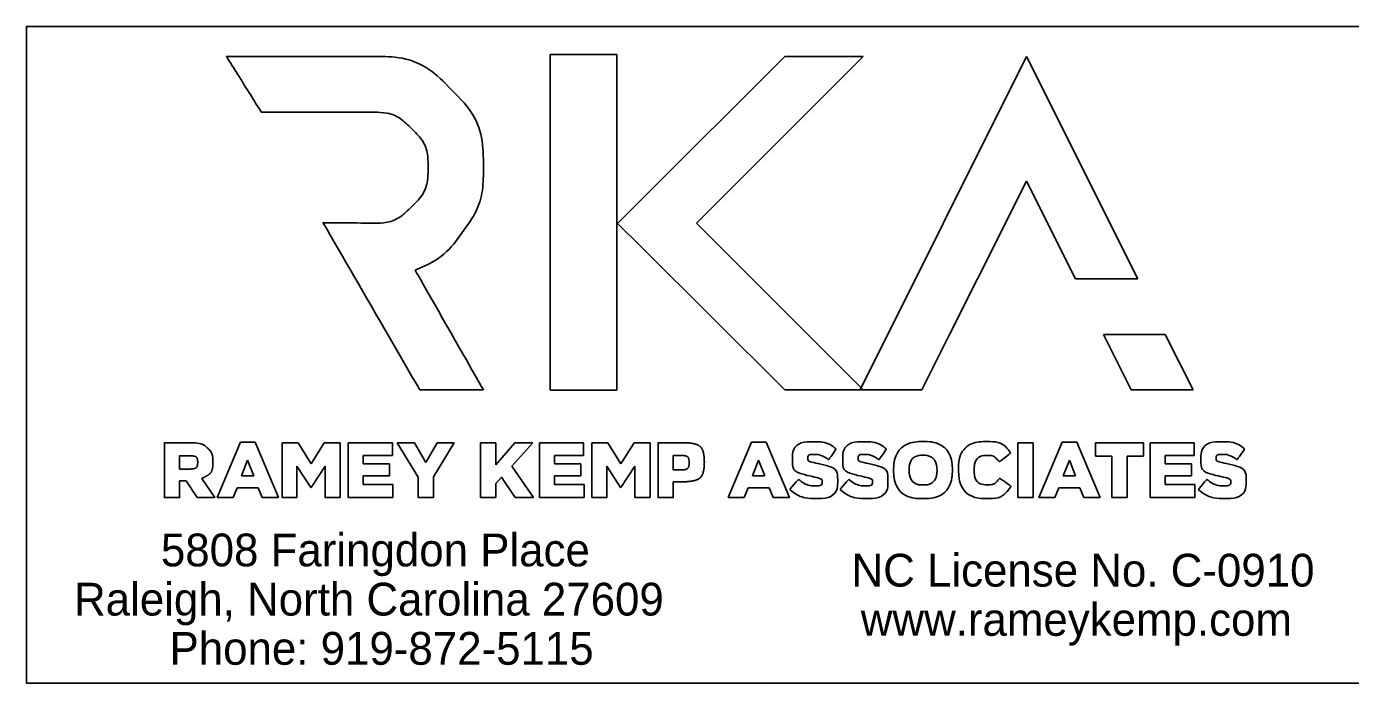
# Model space of a CAD drawing. Extents: x 573078 to 573156.2, y -55225.7 to -55195.8.
# Drawn here: x 573104.512 to 573107.444, y -55197.257 to -55195.798 of the extents above; entities that cross this region are included whole.
import ezdxf

# ---------------------------------------------------------------- set-up
doc = ezdxf.new("R2010")
doc.units = 0
for name, color, linetype in [('Old_Level_60', 7, 'Continuous'), ('Old_Level_61', 7, 'Continuous'), ('Old_Level_62', 7, 'Continuous'), ('Old_Level_63', 7, 'Continuous'), ('Sheet North Arrow Point CELL', 7, 'Continuous'), ('Sheet Plan CELL', 7, 'Continuous')]:
    doc.layers.add(name, color=color, linetype=linetype)

msp = doc.modelspace()

# ---------------------------------------------------------------- linework, layer by layer
at = {"layer": 'Old_Level_60'}
for p, q in [((573105.8198, -55195.8604), (573105.6721, -55195.8604)), ((573105.6721, -55195.8604), (573105.6721, -55196.6033)), ((573105.8198, -55196.6033), (573105.8198, -55195.8604)), ((573105.8727, -55196.183), (573106.1918, -55195.8648)), ((573106.3651, -55195.8648), (573105.9962, -55196.2337)), ((573106.1918, -55195.8648), (573106.3651, -55195.8648)), ((573106.3583, -55196.6026), (573106.7272, -55195.8648)), ((573106.7272, -55195.8648), (573106.9734, -55196.3573)), ((573106.7272, -55196.1406), (573106.6184, -55196.3573)), ((573106.8351, -55196.3573), (573106.7272, -55196.1406)), ((573105.821, -55196.2346), (573105.8727, -55196.183)), ((573105.8727, -55196.2854), (573105.821, -55196.2346)), ((573105.9962, -55196.2337), (573106.3651, -55196.6026)), ((573106.1918, -55196.6026), (573105.8727, -55196.2854)), ((573106.6184, -55196.3573), (573106.5575, -55196.479)), ((573106.9734, -55196.3573), (573106.8351, -55196.3573)), ((573106.5575, -55196.479), (573106.4948, -55196.6026)), ((573105.6721, -55196.6033), (573105.8198, -55196.6033)), ((573106.3651, -55196.6026), (573106.1918, -55196.6026)), ((573106.4948, -55196.6026), (573106.3583, -55196.6026))]:
    msp.add_line(p, q, dxfattribs=at)
msp.add_open_spline([(573105.3731, -55196.3379), (573105.3731, -55196.3379), (573105.5243, -55196.6026), (573105.5243, -55196.6026), (573105.5243, -55196.6026), (573105.3832, -55196.6026), (573105.3832, -55196.6026), (573105.3832, -55196.6026), (573105.1692, -55196.2328), (573105.1692, -55196.2328), (573105.1692, -55196.2328), (573105.279, -55196.2337), (573105.279, -55196.2337), (573105.3122, -55196.2337), (573105.3408, -55196.2217), (573105.3648, -55196.1978), (573105.3897, -55196.1738), (573105.4017, -55196.1443), (573105.4017, -55196.1101), (573105.4017, -55196.0769), (573105.3897, -55196.0484), (573105.3648, -55196.0244), (573105.3408, -55196.0004), (573105.3122, -55195.9884), (573105.279, -55195.9884), (573105.279, -55195.9884), (573105.0328, -55195.9884), (573105.0328, -55195.9884), (573105.0328, -55195.9884), (573104.9553, -55195.8648), (573104.9553, -55195.8648), (573104.9553, -55195.8648), (573105.279, -55195.8648), (573105.279, -55195.8648), (573105.3463, -55195.8648), (573105.4044, -55195.8888), (573105.4524, -55195.9368), (573105.5003, -55195.9856), (573105.5243, -55196.0428), (573105.5243, -55196.1101), (573105.5243, -55196.1618), (573105.5105, -55196.2079), (573105.481, -55196.2494), (573105.4524, -55196.2909), (573105.4164, -55196.3204), (573105.3731, -55196.3379)], degree=3, dxfattribs=at)
at = {"layer": 'Old_Level_61'}
for p, q in [((573106.9587, -55196.6026), (573106.8978, -55196.48)), ((573106.8978, -55196.48), (573107.0343, -55196.48)), ((573107.0343, -55196.48), (573107.0961, -55196.6026)), ((573107.0961, -55196.6026), (573106.9587, -55196.6026))]:
    msp.add_line(p, q, dxfattribs=at)
at = {"layer": 'Old_Level_62'}
for p, q in [((573104.9345, -55196.8412), (573104.9862, -55196.7189)), ((573104.9862, -55196.7189), (573105.0186, -55196.7189)), ((573105.0186, -55196.7189), (573105.0703, -55196.8412)), ((573105.0783, -55196.7198), (573105.1138, -55196.7198)), ((573105.0783, -55196.8412), (573105.0783, -55196.7198)), ((573105.1138, -55196.7198), (573105.1428, -55196.7668)), ((573105.1428, -55196.7668), (573105.1718, -55196.7198)), ((573105.1718, -55196.7198), (573105.2073, -55196.7198)), ((573105.2073, -55196.7198), (573105.2073, -55196.8412)), ((573105.225, -55196.7198), (573105.3226, -55196.7198)), ((573105.225, -55196.8412), (573105.225, -55196.7198)), ((573105.3226, -55196.7198), (573105.3226, -55196.7484)), ((573105.3796, -55196.7958), (573105.3335, -55196.7198)), ((573105.3335, -55196.7198), (573105.3718, -55196.7198)), ((573105.3718, -55196.7198), (573105.3968, -55196.764)), ((573105.3968, -55196.764), (573105.4219, -55196.7198)), ((573105.4596, -55196.7198), (573105.4134, -55196.7953)), ((573105.4219, -55196.7198), (573105.4596, -55196.7198)), ((573105.518, -55196.7198), (573105.5517, -55196.7198)), ((573105.518, -55196.8412), (573105.518, -55196.7198)), ((573105.5517, -55196.7198), (573105.5517, -55196.7691)), ((573105.5517, -55196.7691), (573105.5935, -55196.7198)), ((573105.6334, -55196.7198), (573105.5874, -55196.772)), ((573105.5935, -55196.7198), (573105.6334, -55196.7198)), ((573105.6486, -55196.7198), (573105.7462, -55196.7198)), ((573105.6486, -55196.8412), (573105.6486, -55196.7198)), ((573105.7462, -55196.7198), (573105.7462, -55196.7484)), ((573105.7643, -55196.7198), (573105.7999, -55196.7198)), ((573105.7643, -55196.8412), (573105.7643, -55196.7198)), ((573105.7999, -55196.7198), (573105.8288, -55196.7668)), ((573105.8288, -55196.7668), (573105.8578, -55196.7198)), ((573105.8578, -55196.7198), (573105.8934, -55196.7198)), ((573105.8934, -55196.7198), (573105.8934, -55196.8412)), ((573106.0661, -55196.8412), (573106.1178, -55196.7189)), ((573106.1178, -55196.7189), (573106.1502, -55196.7189)), ((573106.1502, -55196.7189), (573106.2019, -55196.8412)), ((573106.708, -55196.7198), (573106.7418, -55196.7198)), ((573106.708, -55196.8412), (573106.708, -55196.7198)), ((573106.7418, -55196.7198), (573106.7418, -55196.8412)), ((573106.7543, -55196.8412), (573106.806, -55196.7189)), ((573106.806, -55196.7189), (573106.8385, -55196.7189)), ((573106.8385, -55196.7189), (573106.8902, -55196.8412)), ((573106.8796, -55196.7493), (573106.8796, -55196.7198)), ((573106.8796, -55196.7198), (573106.9861, -55196.7198)), ((573106.9861, -55196.7198), (573106.9861, -55196.7493)), ((573107.0008, -55196.7198), (573107.0985, -55196.7198)), ((573107.0008, -55196.8412), (573107.0008, -55196.7198)), ((573107.0985, -55196.7198), (573107.0985, -55196.7484)), ((573104.8916, -55196.7637), (573104.8916, -55196.7633)), ((573104.9254, -55196.7613), (573104.9254, -55196.7616)), ((573105.0022, -55196.7588), (573104.9885, -55196.7934)), ((573105.0157, -55196.7934), (573105.0022, -55196.7588)), ((573105.3226, -55196.7484), (573105.2583, -55196.7484)), ((573105.2583, -55196.7484), (573105.2583, -55196.7668)), ((573105.7462, -55196.7484), (573105.6819, -55196.7484)), ((573105.6819, -55196.7484), (573105.6819, -55196.7668)), ((573105.9799, -55196.7644), (573105.9799, -55196.764)), ((573106.0135, -55196.7625), (573106.0135, -55196.7628)), ((573106.1338, -55196.7588), (573106.12, -55196.7934)), ((573106.1473, -55196.7934), (573106.1338, -55196.7588)), ((573106.822, -55196.7588), (573106.8083, -55196.7934)), ((573106.8355, -55196.7934), (573106.822, -55196.7588)), ((573106.916, -55196.7493), (573106.8796, -55196.7493)), ((573106.916, -55196.8412), (573106.916, -55196.7493)), ((573106.9861, -55196.7493), (573106.9497, -55196.7493)), ((573106.9497, -55196.7493), (573106.9497, -55196.8412)), ((573107.0985, -55196.7484), (573107.0342, -55196.7484)), ((573107.0342, -55196.7484), (573107.0342, -55196.7668)), ((573104.9885, -55196.7934), (573105.0157, -55196.7934)), ((573105.1421, -55196.819), (573105.1112, -55196.7718)), ((573105.1112, -55196.7718), (573105.1112, -55196.8412)), ((573105.1738, -55196.7715), (573105.1428, -55196.819)), ((573105.1738, -55196.8412), (573105.1738, -55196.7715)), ((573105.2583, -55196.7668), (573105.3166, -55196.7668)), ((573105.3166, -55196.7934), (573105.2583, -55196.7934)), ((573105.2583, -55196.7934), (573105.2583, -55196.8126)), ((573105.3166, -55196.7668), (573105.3166, -55196.7934)), ((573105.4134, -55196.7953), (573105.4134, -55196.8412)), ((573105.5874, -55196.772), (573105.635, -55196.8412)), ((573105.6819, -55196.7668), (573105.7402, -55196.7668)), ((573105.7402, -55196.7934), (573105.6819, -55196.7934)), ((573105.6819, -55196.7934), (573105.6819, -55196.8126)), ((573105.7402, -55196.7668), (573105.7402, -55196.7934)), ((573105.8281, -55196.819), (573105.7973, -55196.7718)), ((573105.7973, -55196.7718), (573105.7973, -55196.8412)), ((573105.8599, -55196.7715), (573105.8288, -55196.819)), ((573105.8599, -55196.8412), (573105.8599, -55196.7715)), ((573106.12, -55196.7934), (573106.1473, -55196.7934)), ((573106.4323, -55196.7809), (573106.4323, -55196.7805)), ((573106.4669, -55196.7802), (573106.4669, -55196.7805)), ((573106.5288, -55196.7809), (573106.5288, -55196.7805)), ((573106.5631, -55196.7802), (573106.5631, -55196.7805)), ((573106.8083, -55196.7934), (573106.8355, -55196.7934)), ((573107.0342, -55196.7668), (573107.0924, -55196.7668)), ((573107.0924, -55196.7934), (573107.0342, -55196.7934)), ((573107.0342, -55196.7934), (573107.0342, -55196.8126)), ((573107.0924, -55196.7668), (573107.0924, -55196.7934)), ((573104.9786, -55196.8195), (573104.9699, -55196.8412)), ((573105.0254, -55196.8195), (573104.9786, -55196.8195)), ((573105.0343, -55196.8412), (573105.0254, -55196.8195)), ((573105.1428, -55196.819), (573105.1421, -55196.819)), ((573105.2583, -55196.8126), (573105.3235, -55196.8126)), ((573105.3235, -55196.8126), (573105.3235, -55196.8412)), ((573105.3796, -55196.8412), (573105.3796, -55196.7958)), ((573105.564, -55196.7961), (573105.5517, -55196.8098)), ((573105.5517, -55196.8098), (573105.5517, -55196.8412)), ((573105.5946, -55196.8412), (573105.564, -55196.7961)), ((573105.6819, -55196.8126), (573105.7471, -55196.8126)), ((573105.7471, -55196.8126), (573105.7471, -55196.8412)), ((573105.8288, -55196.819), (573105.8281, -55196.819)), ((573106.1102, -55196.8195), (573106.1015, -55196.8412)), ((573106.157, -55196.8195), (573106.1102, -55196.8195)), ((573106.1658, -55196.8412), (573106.157, -55196.8195)), ((573106.7984, -55196.8195), (573106.7897, -55196.8412)), ((573106.8452, -55196.8195), (573106.7984, -55196.8195)), ((573106.8541, -55196.8412), (573106.8452, -55196.8195)), ((573107.0342, -55196.8126), (573107.0994, -55196.8126)), ((573107.0994, -55196.8126), (573107.0994, -55196.8412)), ((573104.9699, -55196.8412), (573104.9345, -55196.8412)), ((573105.0703, -55196.8412), (573105.0343, -55196.8412)), ((573105.1112, -55196.8412), (573105.0783, -55196.8412)), ((573105.2073, -55196.8412), (573105.1738, -55196.8412)), ((573105.3235, -55196.8412), (573105.225, -55196.8412)), ((573105.4134, -55196.8412), (573105.3796, -55196.8412)), ((573105.5517, -55196.8412), (573105.518, -55196.8412)), ((573105.635, -55196.8412), (573105.5946, -55196.8412)), ((573105.7471, -55196.8412), (573105.6486, -55196.8412)), ((573105.7973, -55196.8412), (573105.7643, -55196.8412)), ((573105.8934, -55196.8412), (573105.8599, -55196.8412)), ((573106.1015, -55196.8412), (573106.0661, -55196.8412)), ((573106.2019, -55196.8412), (573106.1658, -55196.8412)), ((573106.7418, -55196.8412), (573106.708, -55196.8412)), ((573106.7897, -55196.8412), (573106.7543, -55196.8412)), ((573106.8902, -55196.8412), (573106.8541, -55196.8412)), ((573106.9497, -55196.8412), (573106.916, -55196.8412)), ((573107.0994, -55196.8412), (573107.0008, -55196.8412))]:
    msp.add_line(p, q, dxfattribs=at)
for points in [[(573104.9004, -55196.7989), (573104.9294, -55196.8412), (573104.8905, -55196.8412), (573104.8661, -55196.8045), (573104.8657, -55196.8045), (573104.8513, -55196.8045), (573104.8513, -55196.8412), (573104.8177, -55196.8412), (573104.8177, -55196.7198), (573104.8751, -55196.7198)], [(573105.9613, -55196.8065), (573105.9447, -55196.8065), (573105.9447, -55196.8412), (573105.911, -55196.8412), (573105.911, -55196.7198), (573105.963, -55196.7198)], [(573104.8734, -55196.7489), (573104.8513, -55196.7489), (573104.8513, -55196.7781), (573104.8735, -55196.7781)], [(573105.9604, -55196.7481), (573105.9447, -55196.7481), (573105.9447, -55196.7802), (573105.9606, -55196.7802)]]:
    msp.add_lwpolyline(points, dxfattribs=at)
for points, degree in [([(573104.8751, -55196.7198), (573104.8937, -55196.7198), (573104.9065, -55196.7247), (573104.9147, -55196.733), (573104.9218, -55196.7399), (573104.9254, -55196.7493), (573104.9254, -55196.7613)], 3), ([(573105.963, -55196.7198), (573105.9937, -55196.7198), (573106.0135, -55196.7356), (573106.0135, -55196.7625)], 2), ([(573106.2028, -55196.8232), (573106.2028, -55196.8232), (573106.2215, -55196.8008), (573106.2215, -55196.8008), (573106.2335, -55196.8104), (573106.2469, -55196.8154), (573106.2609, -55196.8154), (573106.2699, -55196.8154), (573106.2748, -55196.8123), (573106.2748, -55196.8071), (573106.2748, -55196.8071), (573106.2748, -55196.8067), (573106.2748, -55196.8067), (573106.2748, -55196.8017), (573106.2708, -55196.7989), (573106.2543, -55196.7951), (573106.2285, -55196.7892), (573106.2085, -55196.7819), (573106.2085, -55196.7569), (573106.2085, -55196.7569), (573106.2085, -55196.7566), (573106.2085, -55196.7566), (573106.2085, -55196.734), (573106.2264, -55196.7177), (573106.2555, -55196.7177), (573106.2762, -55196.7177), (573106.2923, -55196.7233), (573106.3055, -55196.7339), (573106.3055, -55196.7339), (573106.2887, -55196.7576), (573106.2887, -55196.7576), (573106.2776, -55196.7498), (573106.2654, -55196.7456), (573106.2547, -55196.7456), (573106.2465, -55196.7456), (573106.2425, -55196.7491), (573106.2425, -55196.7535), (573106.2425, -55196.7535), (573106.2425, -55196.7538), (573106.2425, -55196.7538), (573106.2425, -55196.7594), (573106.2467, -55196.7618), (573106.2635, -55196.7656), (573106.2915, -55196.7717), (573106.3088, -55196.7807), (573106.3088, -55196.8034), (573106.3088, -55196.8034), (573106.3088, -55196.8038), (573106.3088, -55196.8038), (573106.3088, -55196.8286), (573106.2892, -55196.8433), (573106.2597, -55196.8433), (573106.2382, -55196.8433), (573106.2177, -55196.8366), (573106.2028, -55196.8232)], 3), ([(573106.3142, -55196.8232), (573106.3142, -55196.8232), (573106.3329, -55196.8008), (573106.3329, -55196.8008), (573106.3449, -55196.8104), (573106.3582, -55196.8154), (573106.3723, -55196.8154), (573106.3813, -55196.8154), (573106.3862, -55196.8123), (573106.3862, -55196.8071), (573106.3862, -55196.8071), (573106.3862, -55196.8067), (573106.3862, -55196.8067), (573106.3862, -55196.8017), (573106.3822, -55196.7989), (573106.3657, -55196.7951), (573106.3399, -55196.7892), (573106.3199, -55196.7819), (573106.3199, -55196.7569), (573106.3199, -55196.7569), (573106.3199, -55196.7566), (573106.3199, -55196.7566), (573106.3199, -55196.734), (573106.3378, -55196.7177), (573106.3669, -55196.7177), (573106.3876, -55196.7177), (573106.4037, -55196.7233), (573106.4169, -55196.7339), (573106.4169, -55196.7339), (573106.4001, -55196.7576), (573106.4001, -55196.7576), (573106.3889, -55196.7498), (573106.3768, -55196.7456), (573106.3661, -55196.7456), (573106.3579, -55196.7456), (573106.3539, -55196.7491), (573106.3539, -55196.7535), (573106.3539, -55196.7535), (573106.3539, -55196.7538), (573106.3539, -55196.7538), (573106.3539, -55196.7594), (573106.3581, -55196.7618), (573106.3749, -55196.7656), (573106.4028, -55196.7717), (573106.4202, -55196.7807), (573106.4202, -55196.8034), (573106.4202, -55196.8034), (573106.4202, -55196.8038), (573106.4202, -55196.8038), (573106.4202, -55196.8286), (573106.4006, -55196.8433), (573106.3711, -55196.8433), (573106.3496, -55196.8433), (573106.3291, -55196.8366), (573106.3142, -55196.8232)], 3), ([(573106.4323, -55196.7805), (573106.4323, -55196.7456), (573106.4604, -55196.7174), (573106.4979, -55196.7174), (573106.5354, -55196.7174), (573106.5631, -55196.7453), (573106.5631, -55196.7802)], 3), ([(573106.5765, -55196.7809), (573106.5765, -55196.7809), (573106.5765, -55196.7805), (573106.5765, -55196.7805), (573106.5765, -55196.7451), (573106.6037, -55196.7174), (573106.6405, -55196.7174), (573106.6653, -55196.7174), (573106.6813, -55196.7278), (573106.692, -55196.7427), (573106.692, -55196.7427), (573106.6667, -55196.7623), (573106.6667, -55196.7623), (573106.6598, -55196.7536), (573106.6518, -55196.7481), (573106.6402, -55196.7481), (573106.6232, -55196.7481), (573106.6112, -55196.7625), (573106.6112, -55196.7802), (573106.6112, -55196.7802), (573106.6112, -55196.7805), (573106.6112, -55196.7805), (573106.6112, -55196.7987), (573106.6232, -55196.813), (573106.6402, -55196.813), (573106.6528, -55196.813), (573106.6603, -55196.8071), (573106.6676, -55196.7982), (573106.6676, -55196.7982), (573106.6929, -55196.8163), (573106.6929, -55196.8163), (573106.6814, -55196.832), (573106.666, -55196.8437), (573106.6391, -55196.8437), (573106.6044, -55196.8437), (573106.5765, -55196.8171), (573106.5765, -55196.7809)], 3), ([(573107.1074, -55196.8232), (573107.1074, -55196.8232), (573107.1261, -55196.8008), (573107.1261, -55196.8008), (573107.1381, -55196.8104), (573107.1514, -55196.8154), (573107.1655, -55196.8154), (573107.1745, -55196.8154), (573107.1794, -55196.8123), (573107.1794, -55196.8071), (573107.1794, -55196.8071), (573107.1794, -55196.8067), (573107.1794, -55196.8067), (573107.1794, -55196.8017), (573107.1754, -55196.7989), (573107.1589, -55196.7951), (573107.133, -55196.7892), (573107.1131, -55196.7819), (573107.1131, -55196.7569), (573107.1131, -55196.7569), (573107.1131, -55196.7566), (573107.1131, -55196.7566), (573107.1131, -55196.734), (573107.131, -55196.7177), (573107.1601, -55196.7177), (573107.1807, -55196.7177), (573107.1969, -55196.7233), (573107.2101, -55196.7339), (573107.2101, -55196.7339), (573107.1932, -55196.7576), (573107.1932, -55196.7576), (573107.1821, -55196.7498), (573107.17, -55196.7456), (573107.1592, -55196.7456), (573107.1511, -55196.7456), (573107.1471, -55196.7491), (573107.1471, -55196.7535), (573107.1471, -55196.7535), (573107.1471, -55196.7538), (573107.1471, -55196.7538), (573107.1471, -55196.7594), (573107.1513, -55196.7618), (573107.1681, -55196.7656), (573107.196, -55196.7717), (573107.2134, -55196.7807), (573107.2134, -55196.8034), (573107.2134, -55196.8034), (573107.2134, -55196.8038), (573107.2134, -55196.8038), (573107.2134, -55196.8286), (573107.1938, -55196.8433), (573107.1643, -55196.8433), (573107.1428, -55196.8433), (573107.1223, -55196.8366), (573107.1074, -55196.8232)], 3), ([(573104.8916, -55196.7633), (573104.8916, -55196.7538), (573104.8846, -55196.7489), (573104.8734, -55196.7489)], 2), ([(573104.8735, -55196.7781), (573104.885, -55196.7781), (573104.8916, -55196.7725), (573104.8916, -55196.7637)], 2), ([(573104.9254, -55196.7616), (573104.9254, -55196.7802), (573104.9155, -55196.7925), (573104.9004, -55196.7989)], 2), ([(573105.9799, -55196.764), (573105.9799, -55196.7536), (573105.9726, -55196.7481), (573105.9604, -55196.7481)], 2), ([(573105.9606, -55196.7802), (573105.9726, -55196.7802), (573105.9799, -55196.7739), (573105.9799, -55196.7644)], 2), ([(573106.0135, -55196.7628), (573106.0135, -55196.7914), (573105.9915, -55196.8065), (573105.9613, -55196.8065)], 2), ([(573106.5288, -55196.7805), (573106.5288, -55196.763), (573106.5161, -55196.7477), (573106.4976, -55196.7477), (573106.4792, -55196.7477), (573106.4669, -55196.7626), (573106.4669, -55196.7802)], 3), ([(573106.5631, -55196.7805), (573106.5631, -55196.8154), (573106.535, -55196.8437), (573106.4976, -55196.8437), (573106.4601, -55196.8437), (573106.4323, -55196.8157), (573106.4323, -55196.7809)], 3), ([(573106.4669, -55196.7805), (573106.4669, -55196.798), (573106.4795, -55196.8133), (573106.4979, -55196.8133), (573106.5165, -55196.8133), (573106.5288, -55196.7984), (573106.5288, -55196.7809)], 3)]:
    msp.add_open_spline(points, degree=degree, dxfattribs=at)
at = {"layer": 'Sheet North Arrow Point CELL'}
msp.add_line((573106.1518, -55197.2574), (573106.1518, -55197.2574), dxfattribs=at)
at = {"layer": 'Sheet Plan CELL'}
msp.add_lwpolyline([(573107.5132, -55197.252), (573104.5124, -55197.252), (573104.5124, -55195.7984), (573107.5132, -55195.7984)], close=True, dxfattribs=at)

# ---------------------------------------------------------------- texts
at = {"layer": 'Old_Level_63'}
for s, p in [('5808 Faringdon Place', (573104.8101, -55196.9936)), ('NC License No. C-0910', (573106.3394, -55197.0384)), ('Raleigh, North Carolina 27609', (573104.6177, -55197.1025)), ('www.rameykemp.com', (573106.3599, -55197.1473)), ('Phone: 919-872-5115', (573104.8292, -55197.2114))]:
    msp.add_text(s, height=0.0726, dxfattribs=at).set_placement(p)

doc.saveas('drawing.dxf')
